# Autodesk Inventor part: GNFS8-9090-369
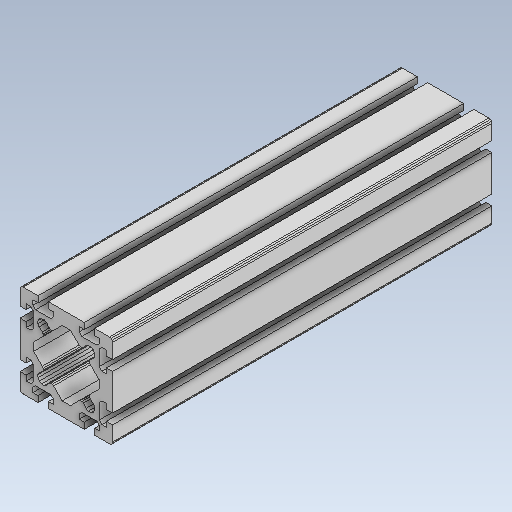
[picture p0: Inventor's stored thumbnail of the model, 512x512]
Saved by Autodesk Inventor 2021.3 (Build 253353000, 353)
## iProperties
Created: 2022-02
Part Number: GNFS8-9090-369
Material: 一般
Document SubType Name: Modeling
Designer: kengo
Density: 1 g/cm^3
Appearance: 既定
Author: kengo
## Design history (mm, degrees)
feature "GNFS8-9090-369"
node "ソリッド1"
